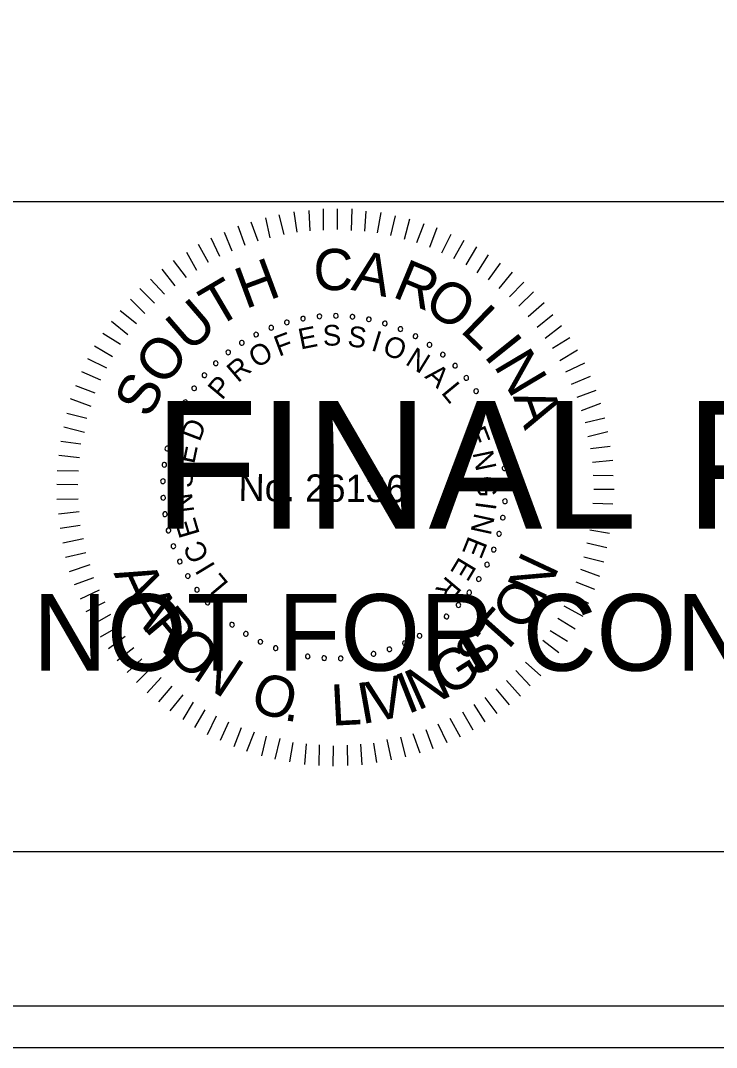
# Model space of a CAD drawing. Extents: x 967 to 1326, y 964 to 2584.
# Drawn here: x 1170.56 to 1189.3, y 1803.72 to 1831.36 of the extents above; entities that cross this region are included whole.
import ezdxf

# ---------------------------------------------------------------- set-up
doc = ezdxf.new("R2010")
doc.units = 0
for name, color, linetype in [('RD_SHT_Bndy', 7, 'Continuous'), ('RD_SHT_IplotShp', 7, 'Continuous'), ('RD_SHT_Misc1', 7, 'Continuous'), ('RD_SHT_Misc2', 7, 'Continuous'), ('RD_Sketch1', 7, 'Continuous')]:
    doc.layers.add(name, color=color, linetype=linetype)

msp = doc.modelspace()

# ---------------------------------------------------------------- linework, layer by layer
at = {"layer": 'RD_SHT_Bndy'}
for p, q in [((996.114, 1826.486), (1323.886, 1826.486)), ((1323.886, 1808.983), (996.114, 1808.983))]:
    msp.add_line(p, q, dxfattribs=at)
at = {"layer": 'RD_SHT_IplotShp'}
for points in [[(967.409, 1803.72), (1326.285, 1803.72), (1326.285, 2023.72), (967.409, 2023.72)], [(988.525, 1804.84), (1326.285, 1804.84), (1326.285, 2022.6), (988.525, 2022.6)]]:
    msp.add_lwpolyline(points, close=True, dxfattribs=at)
at = {"layer": 'RD_SHT_Misc1'}
for p, q in [((1178.01, 1825.663), (1177.93, 1826.209)), ((1178.364, 1825.699), (1178.33, 1826.244)), ((1178.717, 1825.719), (1178.722, 1826.295)), ((1179.093, 1825.739), (1179.098, 1826.292)), ((1179.469, 1825.713), (1179.489, 1826.288)), ((1179.829, 1825.687), (1179.872, 1826.231)), ((1180.174, 1825.646), (1180.271, 1826.19)), ((1176.964, 1825.419), (1176.769, 1825.935)), ((1177.287, 1825.508), (1177.169, 1826.054)), ((1177.657, 1825.597), (1177.53, 1826.128)), ((1180.535, 1825.573), (1180.662, 1826.102)), ((1180.902, 1825.478), (1181.045, 1826.022)), ((1181.231, 1825.384), (1181.428, 1825.896)), ((1176.264, 1825.156), (1176.053, 1825.657)), ((1176.61, 1825.306), (1176.423, 1825.83)), ((1181.584, 1825.265), (1181.78, 1825.786)), ((1181.905, 1825.109), (1182.154, 1825.606)), ((1175.624, 1824.846), (1175.352, 1825.332)), ((1175.933, 1825.005), (1175.699, 1825.506)), ((1182.226, 1824.953), (1182.506, 1825.45)), ((1175.308, 1824.634), (1175.036, 1825.12)), ((1182.562, 1824.789), (1182.85, 1825.27)), ((1175.03, 1824.445), (1174.681, 1824.9)), ((1182.86, 1824.572), (1183.163, 1825.053)), ((1183.158, 1824.378), (1183.484, 1824.828)), ((1174.729, 1824.217), (1174.372, 1824.665)), ((1183.447, 1824.145), (1183.811, 1824.587)), ((1174.435, 1823.997), (1174.062, 1824.399)), ((1183.729, 1823.92), (1184.116, 1824.316)), ((1174.172, 1823.753), (1173.776, 1824.148)), ((1183.98, 1823.672), (1184.368, 1824.061)), ((1173.909, 1823.479), (1173.52, 1823.858)), ((1184.232, 1823.394), (1184.657, 1823.767)), ((1173.684, 1823.197), (1173.242, 1823.546)), ((1184.475, 1823.108), (1184.892, 1823.45)), ((1173.451, 1822.9), (1173.009, 1823.256)), ((1184.687, 1822.807), (1185.128, 1823.156)), ((1173.257, 1822.64), (1172.776, 1822.936)), ((1173.039, 1822.312), (1172.559, 1822.6)), ((1184.885, 1822.544), (1185.355, 1822.832)), ((1185.081, 1822.213), (1185.56, 1822.493)), ((1172.883, 1822.006), (1172.379, 1822.256)), ((1185.24, 1821.904), (1185.756, 1822.145)), ((1172.727, 1821.677), (1172.215, 1821.904)), ((1185.399, 1821.573), (1185.907, 1821.791)), ((1172.571, 1821.333), (1172.051, 1821.53)), ((1185.549, 1821.226), (1186.057, 1821.414)), ((1172.461, 1820.974), (1171.91, 1821.178)), ((1185.669, 1820.865), (1186.185, 1821.06)), ((1172.351, 1820.652), (1171.807, 1820.787)), ((1185.759, 1820.541), (1186.297, 1820.667)), ((1172.286, 1820.276), (1171.727, 1820.419)), ((1185.832, 1820.165), (1186.371, 1820.298)), ((1172.191, 1819.955), (1171.647, 1820.029)), ((1185.906, 1819.842), (1186.436, 1819.906)), ((1172.15, 1819.587), (1171.598, 1819.653)), ((1185.964, 1819.473), (1186.51, 1819.53)), ((1172.124, 1819.234), (1171.548, 1819.239)), ((1185.977, 1819.12), (1186.514, 1819.115)), ((1172.105, 1818.866), (1171.545, 1818.871)), ((1185.997, 1818.751), (1186.542, 1818.747)), ((1172.118, 1818.482), (1171.542, 1818.471)), ((1185.971, 1818.368), (1186.508, 1818.348)), ((1172.138, 1818.136), (1171.585, 1818.072)), ((1185.952, 1818.022), (1186.497, 1817.949)), ((1172.173, 1817.768), (1171.627, 1817.688)), ((1185.888, 1817.655), (1186.417, 1817.566)), ((1172.262, 1817.414), (1171.701, 1817.296)), ((1185.808, 1817.302), (1186.345, 1817.175)), ((1172.321, 1817.037), (1171.774, 1816.911)), ((1185.729, 1816.926), (1186.265, 1816.792)), ((1172.425, 1816.707), (1171.871, 1816.519)), ((1185.634, 1816.597), (1186.146, 1816.401)), ((1172.53, 1816.36), (1172.007, 1816.173)), ((1185.508, 1816.253), (1186.013, 1816.057)), ((1172.681, 1816.029), (1172.165, 1815.788)), ((1172.831, 1815.705), (1172.323, 1815.441)), ((1185.352, 1815.924), (1185.857, 1815.675)), ((1185.188, 1815.603), (1185.7, 1815.33)), ((1172.982, 1815.374), (1172.497, 1815.094)), ((1185.024, 1815.274), (1185.498, 1814.987)), ((1173.194, 1815.042), (1172.709, 1814.762)), ((1184.822, 1814.946), (1185.288, 1814.658)), ((1173.384, 1814.78), (1172.936, 1814.453)), ((1184.62, 1814.687), (1185.055, 1814.353)), ((1173.612, 1814.478), (1173.164, 1814.129)), ((1184.403, 1814.389), (1184.814, 1814.033)), ((1173.832, 1814.177), (1173.437, 1813.812)), ((1184.155, 1814.092), (1184.574, 1813.72)), ((1174.091, 1813.945), (1173.689, 1813.541)), ((1183.899, 1813.864), (1184.28, 1813.454)), ((1174.35, 1813.674), (1173.97, 1813.263)), ((1183.644, 1813.597), (1184.024, 1813.18)), ((1174.64, 1813.442), (1174.275, 1813.022)), ((1174.937, 1813.209), (1174.58, 1812.782)), ((1183.358, 1813.37), (1183.715, 1812.944)), ((1175.212, 1813.014), (1174.932, 1812.549)), ((1182.764, 1812.952), (1183.059, 1812.482)), ((1183.065, 1813.141), (1183.384, 1812.709)), ((1175.525, 1812.812), (1175.245, 1812.331)), ((1175.83, 1812.633), (1175.588, 1812.136)), ((1182.463, 1812.755), (1182.743, 1812.269)), ((1176.159, 1812.477), (1175.94, 1811.98)), ((1181.8, 1812.431), (1182.041, 1811.93)), ((1182.124, 1812.581), (1182.396, 1812.08)), ((1176.503, 1812.321), (1176.307, 1811.816)), ((1176.855, 1812.211), (1176.651, 1811.69)), ((1177.177, 1812.1), (1177.05, 1811.572)), ((1180.791, 1812.07), (1180.926, 1811.54)), ((1181.122, 1812.175), (1181.31, 1811.652)), ((1181.476, 1812.28), (1181.664, 1811.771)), ((1177.545, 1812.036), (1177.409, 1811.484)), ((1177.897, 1811.933), (1177.808, 1811.412)), ((1178.25, 1811.892), (1178.207, 1811.34)), ((1178.603, 1811.866), (1178.598, 1811.313)), ((1178.978, 1811.84), (1178.974, 1811.295)), ((1179.355, 1811.86), (1179.365, 1811.307)), ((1179.715, 1811.88), (1179.749, 1811.327)), ((1180.061, 1811.915), (1180.149, 1811.393)), ((1180.423, 1812.012), (1180.541, 1811.458))]:
    msp.add_line(p, q, dxfattribs=at)
for centre, start, end in [((1178.168, 1823.337), 10.6038, 190.6038), ((1178.609, 1823.397), 5.0653, 185.0653), ((1178.609, 1823.397), 185.0653, 5.0653), ((1179.055, 1823.414), 359.5268, 179.5268), ((1179.055, 1823.414), 179.5268, 359.5268), ((1179.5, 1823.388), 353.9884, 173.9884), ((1177.312, 1823.091), 21.6807, 201.6807), ((1177.734, 1823.235), 16.1422, 196.1422), ((1177.734, 1823.235), 196.1422, 16.1422), ((1178.168, 1823.337), 190.6038, 10.6038), ((1179.5, 1823.388), 173.9884, 353.9884), ((1179.94, 1823.319), 168.4499, 348.4499), ((1179.94, 1823.319), 348.4499, 168.4499), ((1180.372, 1823.208), 162.9114, 342.9114), ((1180.372, 1823.208), 342.9114, 162.9114), ((1180.79, 1823.056), 337.373, 157.373), ((1176.906, 1822.908), 27.2191, 207.2191), ((1176.906, 1822.908), 207.2191, 27.2191), ((1177.312, 1823.091), 201.6807, 21.6807), ((1180.79, 1823.056), 157.373, 337.373), ((1181.193, 1822.864), 151.8345, 331.8345), ((1181.193, 1822.864), 331.8345, 151.8345), ((1176.52, 1822.686), 32.7576, 212.7576), ((1176.52, 1822.686), 212.7576, 32.7576), ((1181.574, 1822.634), 146.2961, 326.2961), ((1181.574, 1822.634), 326.2961, 146.2961), ((1176.156, 1822.428), 38.2961, 218.2961), ((1176.156, 1822.428), 218.2961, 38.2961), ((1181.932, 1822.368), 140.7576, 320.7576), ((1181.932, 1822.368), 320.7576, 140.7576), ((1175.82, 1822.135), 43.8345, 223.8345), ((1175.82, 1822.135), 223.8345, 43.8345), ((1182.263, 1822.069), 135.2191, 315.2191), ((1182.263, 1822.069), 315.2191, 135.2191), ((1175.513, 1821.812), 49.373, 229.373), ((1175.513, 1821.812), 229.373, 49.373), ((1182.563, 1821.74), 129.6807, 309.6807), ((1182.563, 1821.74), 309.6807, 129.6807), ((1175.239, 1821.461), 54.9114, 234.9114), ((1175.239, 1821.461), 234.9114, 54.9114), ((1182.83, 1821.383), 124.1422, 304.1422), ((1182.83, 1821.383), 304.1422, 124.1422), ((1175, 1821.085), 60.4499, 240.4499), ((1175, 1821.085), 240.4499, 60.4499), ((1183.061, 1821.002), 118.6038, 298.6038), ((1183.061, 1821.002), 298.6038, 118.6038), ((1174.798, 1820.687), 65.9884, 245.9884), ((1174.798, 1820.687), 245.9884, 65.9884), ((1183.255, 1820.601), 113.0653, 293.0653), ((1183.255, 1820.601), 293.0653, 113.0653), ((1174.636, 1820.272), 71.5268, 251.5268), ((1174.636, 1820.272), 251.5268, 71.5268), ((1183.408, 1820.182), 107.5268, 287.5268), ((1183.408, 1820.182), 287.5268, 107.5268), ((1174.514, 1819.843), 77.0653, 257.0653), ((1174.514, 1819.843), 257.0653, 77.0653), ((1183.521, 1819.751), 101.9884, 281.9884), ((1183.521, 1819.751), 281.9884, 101.9884), ((1174.435, 1819.405), 82.6038, 262.6038), ((1174.435, 1819.405), 262.6038, 82.6038), ((1183.592, 1819.311), 96.4499, 276.4499), ((1183.592, 1819.311), 276.4499, 96.4499), ((1174.398, 1818.961), 88.1422, 268.1422), ((1174.398, 1818.961), 268.1422, 88.1422), ((1183.619, 1818.866), 90.9114, 270.9114), ((1183.619, 1818.866), 270.9114, 90.9114), ((1174.404, 1818.515), 93.6807, 273.6807), ((1174.404, 1818.515), 273.6807, 93.6807), ((1183.604, 1818.421), 85.373, 265.373), ((1183.604, 1818.421), 265.373, 85.373), ((1174.453, 1818.072), 99.2191, 279.2191), ((1174.453, 1818.072), 279.2191, 99.2191), ((1183.546, 1817.979), 79.8345, 259.8345), ((1183.546, 1817.979), 259.8345, 79.8345), ((1174.545, 1817.636), 104.7576, 284.7576), ((1174.545, 1817.636), 284.7576, 104.7576), ((1183.445, 1817.545), 74.2961, 254.2961), ((1183.445, 1817.545), 254.2961, 74.2961), ((1174.678, 1817.211), 110.2961, 290.2961), ((1174.678, 1817.211), 290.2961, 110.2961), ((1183.303, 1817.122), 68.7576, 248.7576), ((1183.303, 1817.122), 248.7576, 68.7576), ((1174.852, 1816.8), 115.8345, 295.8345), ((1174.852, 1816.8), 295.8345, 115.8345), ((1183.121, 1816.716), 63.2191, 243.2191), ((1183.121, 1816.716), 243.2191, 63.2191), ((1175.065, 1816.409), 121.373, 301.373), ((1175.065, 1816.409), 301.373, 121.373), ((1182.9, 1816.328), 57.6807, 237.6807), ((1182.9, 1816.328), 237.6807, 57.6807), ((1175.314, 1816.039), 126.9114, 306.9114), ((1175.314, 1816.039), 306.9114, 126.9114), ((1182.643, 1815.964), 52.1422, 232.1422), ((1182.643, 1815.964), 232.1422, 52.1422), ((1175.598, 1815.696), 132.4499, 312.4499), ((1175.598, 1815.696), 312.4499, 132.4499), ((1182.353, 1815.627), 46.6038, 226.6038), ((1182.353, 1815.627), 226.6038, 46.6038), ((1175.914, 1815.381), 137.9884, 317.9884), ((1175.914, 1815.381), 317.9884, 137.9884), ((1182.03, 1815.319), 41.0653, 221.0653), ((1176.258, 1815.099), 143.5268, 323.5268), ((1176.258, 1815.099), 323.5268, 143.5268), ((1181.68, 1815.043), 35.5268, 215.5268), ((1182.03, 1815.319), 221.0653, 41.0653), ((1176.629, 1814.851), 149.0653, 329.0653), ((1176.629, 1814.851), 329.0653, 149.0653), ((1181.305, 1814.803), 29.9884, 209.9884), ((1181.305, 1814.803), 209.9884, 29.9884), ((1181.68, 1815.043), 215.5268, 35.5268), ((1177.021, 1814.639), 154.6038, 334.6038), ((1177.021, 1814.639), 334.6038, 154.6038), ((1180.908, 1814.6), 24.4499, 204.4499), ((1180.908, 1814.6), 204.4499, 24.4499), ((1177.432, 1814.467), 160.1422, 340.1422), ((1177.432, 1814.467), 340.1422, 160.1422), ((1177.858, 1814.335), 165.6807, 345.6807), ((1177.858, 1814.335), 345.6807, 165.6807), ((1178.294, 1814.245), 351.2191, 171.2191), ((1179.627, 1814.232), 7.8345, 187.8345), ((1180.065, 1814.313), 13.373, 193.373), ((1180.065, 1814.313), 193.373, 13.373), ((1180.494, 1814.436), 18.9114, 198.9114), ((1180.494, 1814.436), 198.9114, 18.9114), ((1178.294, 1814.245), 171.2191, 351.2191), ((1178.737, 1814.198), 356.7576, 176.7576), ((1178.737, 1814.198), 176.7576, 356.7576), ((1179.183, 1814.193), 2.2961, 182.2961), ((1179.183, 1814.193), 182.2961, 2.2961), ((1179.627, 1814.232), 187.8345, 7.8345)]:
    msp.add_arc(centre, 0.0627, start, end, dxfattribs=at)
at = {"layer": 'RD_Sketch1'}
msp.add_lwpolyline([(967.409, 1803.72), (1326.285, 1803.72), (1326.285, 2023.72), (967.409, 2023.72)], close=True, dxfattribs=at)

# ---------------------------------------------------------------- texts
at = {"layer": 'RD_SHT_Misc1'}
for s, height, rotation, p in [('C', 1.11, 359.5482, (1178.442, 1824.108)), ('A', 1.11, 348.1981, (1179.439, 1824.115)), ('H', 1.11, 20.3637, (1176.614, 1823.587)), ('R', 1.11, 337.4344, (1180.541, 1823.937)), ('T', 1.11, 30.4992, (1175.828, 1823.072)), ('O', 1.108, 326.5869, (1181.366, 1823.609)), ('U', 1.11, 40.8022, (1175.102, 1822.403)), ('L', 1.11, 315.9488, (1182.373, 1823.003)), ('E', 0.557, 11.4103, (1178.103, 1822.503)), ('S', 0.557, 2.208, (1178.709, 1822.601)), ('S', 0.557, 352.6608, (1179.346, 1822.599)), ('O', 1.11, 52.0267, (1174.435, 1821.474)), ('F', 0.557, 20.6127, (1177.52, 1822.309)), ('I', 0.557, 343.1136, (1179.975, 1822.491)), ('O', 0.557, 338.4392, (1180.274, 1822.401)), ('I', 1.11, 308.6613, (1183.011, 1822.338)), ('O', 0.557, 30.8477, (1176.917, 1821.987)), ('N', 0.557, 328.2042, (1180.896, 1822.12)), ('N', 1.11, 300.7037, (1183.285, 1822.075)), ('R', 0.557, 40.3949, (1176.415, 1821.594)), ('A', 0.557, 318.657, (1181.424, 1821.762)), ('S', 1.108, 63.2511, (1174.029, 1820.619)), ('P', 0.557, 49.9421, (1175.985, 1821.124)), ('L', 0.557, 309.4546, (1181.869, 1821.339)), ('A', 1.11, 289.4792, (1183.814, 1821.243)), ('D', 0.557, 69.0364, (1175.386, 1820.003)), ('E', 0.557, 291.049, (1182.53, 1820.307)), ('E', 0.557, 78.2388, (1175.238, 1819.407)), ('N', 0.557, 281.8466, (1182.728, 1819.726)), ('S', 0.557, 87.786, (1175.187, 1818.772)), ('No. 26136', 0.7311, 359.5268, (1176.429, 1818.43)), ('G', 0.557, 272.2995, (1182.833, 1819.097)), ('N', 0.557, 97.3332, (1175.242, 1818.137)), ('I', 0.557, 262.4084, (1182.83, 1818.437)), ('E', 0.557, 106.5355, (1175.394, 1817.541)), ('N', 0.557, 257.7339, (1182.789, 1818.127)), ('C', 0.557, 116.4266, (1175.661, 1816.938)), ('E', 0.557, 248.1867, (1182.628, 1817.511)), ('I', 0.557, 121.1011, (1175.823, 1816.67)), ('E', 0.557, 238.9844, (1182.378, 1816.949)), ('N', 1.105, 64.8922, (1184.632, 1815.684)), ('A', 1.105, 294.7297, (1173.062, 1816.486)), ('L', 0.557, 129.9595, (1176.187, 1816.204)), ('R', 0.557, 229.782, (1182.041, 1816.435)), ('O', 1.105, 56.2059, (1184.102, 1814.874)), ('A', 1.105, 302.2892, (1173.414, 1815.72)), ('R', 1.105, 309.8487, (1173.865, 1815.007)), ('T', 1.105, 48.2685, (1183.515, 1814.211)), ('O', 1.105, 317.7861, (1174.434, 1814.33)), ('S', 1.105, 40.3311, (1182.842, 1813.636)), ('N', 1.105, 326.4725, (1175.158, 1813.686)), ('G', 1.105, 32.0198, (1182.059, 1813.14)), ('N', 1.105, 24.0824, (1181.252, 1812.776)), ('O', 1.105, 342.3472, (1176.697, 1812.82)), ('V', 1.105, 12.7741, (1180.033, 1812.457)), ('I', 1.105, 21.4605, (1180.976, 1812.681)), ('L', 1.105, 2.9677, (1178.943, 1812.379)), ('I', 1.105, 10.1523, (1179.743, 1812.418)), ('.', 1.105, 351.0336, (1177.623, 1812.536))]:
    msp.add_text(s, height=height, rotation=rotation, dxfattribs=at).set_placement(p)
at = {"layer": 'RD_SHT_Misc2'}
for s, height, p in [('FINAL PLANS', 3.4375, (1174.145, 1817.685)), ('NOT FOR CONSTRUCTION', 2.0625, (1170.901, 1813.86))]:
    msp.add_text(s, height=height, dxfattribs=at).set_placement(p)

doc.saveas('drawing.dxf')
